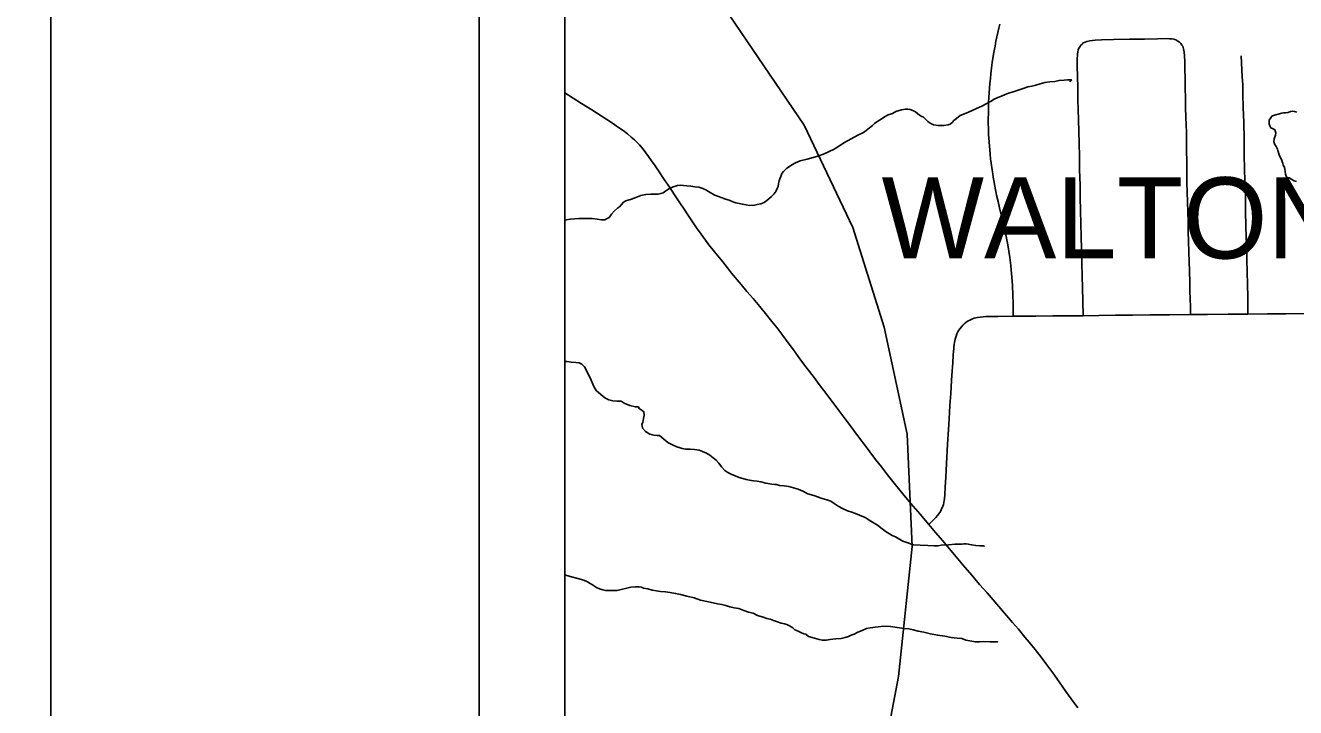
# Model space of a CAD drawing. Extents: x 0 to 34, y 0 to 22.
# Drawn here: x 1.47 to 2.953, y 15.914 to 16.711 of the extents above; entities that cross this region are included whole.
import ezdxf

# ---------------------------------------------------------------- set-up
doc = ezdxf.new("R2010")
doc.units = 0
for name, color, linetype in [('GM_X_City_Street', 7, 'Continuous'), ('GM_X_Corporation_Text', 7, 'Continuous'), ('GM_X_County_Road', 7, 'Continuous'), ('GM_X_County_Text', 7, 'Continuous'), ('GM_X_Minor_Lake', 7, 'Continuous'), ('GM_X_Minor_River', 7, 'Continuous'), ('GM_X_Rail_Line', 7, 'Continuous'), ('SH_Border', 7, 'Continuous'), ('SH_Cut_Line', 7, 'Continuous'), ('SH_Data', 7, 'Continuous')]:
    doc.layers.add(name, color=color, linetype=linetype)

msp = doc.modelspace()

# ---------------------------------------------------------------- linework, layer by layer
at = {"layer": 'GM_X_City_Street'}
for points in [[(2.623, 16.3712), (2.6229, 16.3858), (2.6226, 16.3959), (2.6222, 16.4073), (2.6216, 16.417), (2.6209, 16.4256), (2.6203, 16.4304), (2.6191, 16.44), (2.618, 16.4472), (2.6167, 16.4545), (2.6149, 16.4644), (2.6125, 16.4755), (2.6107, 16.4831), (2.6073, 16.4978), (2.6054, 16.5052), (2.6038, 16.5126), (2.6017, 16.5232), (2.6004, 16.5296), (2.5998, 16.5338), (2.5992, 16.5375), (2.5985, 16.542), (2.5974, 16.5501), (2.5968, 16.5551), (2.5963, 16.5605), (2.595, 16.5747), (2.5944, 16.5833), (2.5942, 16.5875), (2.5941, 16.5916), (2.594, 16.5956), (2.5941, 16.6143), (2.5943, 16.6178), (2.5944, 16.6213), (2.5948, 16.6267), (2.5951, 16.6321), (2.5955, 16.6375), (2.596, 16.6431), (2.5965, 16.6488), (2.597, 16.6544), (2.5974, 16.6577), (2.5978, 16.661), (2.5982, 16.6643), (2.5987, 16.6676), (2.5998, 16.675), (2.6005, 16.6791), (2.6013, 16.6832), (2.6019, 16.6864), (2.603, 16.6923), (2.6041, 16.6973), (2.6052, 16.7024), (2.6063, 16.7074), (2.6075, 16.7124)], [(2.7011, 16.6863), (2.7022, 16.6878), (2.7035, 16.6891), (2.7048, 16.6903), (2.7069, 16.6914), (2.7091, 16.6922), (2.7124, 16.6928), (2.7156, 16.6933), (2.7189, 16.6936), (2.7261, 16.694), (2.7402, 16.6942), (2.759, 16.6946), (2.7762, 16.6949), (2.7914, 16.6952), (2.8022, 16.6954), (2.8054, 16.6953), (2.8078, 16.6951), (2.8104, 16.6946), (2.8129, 16.6938), (2.8151, 16.6926), (2.817, 16.6913), (2.8186, 16.6897), (2.8199, 16.6879), (2.821, 16.6864)], [(2.7046, 16.3719), (2.7042, 16.3892), (2.7038, 16.4044), (2.7035, 16.4179), (2.7032, 16.4336), (2.7028, 16.4494), (2.7024, 16.4646), (2.7021, 16.4795), (2.7018, 16.4942), (2.7014, 16.5097), (2.7011, 16.5243), (2.7006, 16.542), (2.7003, 16.558), (2.6999, 16.5728), (2.6996, 16.5872), (2.6993, 16.6), (2.699, 16.6131), (2.6987, 16.624), (2.6984, 16.6375), (2.6981, 16.6518), (2.6978, 16.6625), (2.6977, 16.6709), (2.698, 16.6773), (2.6984, 16.6798), (2.699, 16.6822), (2.6998, 16.6842), (2.7011, 16.6863)], [(2.8301, 16.3733), (2.8298, 16.3827), (2.8296, 16.3913), (2.8293, 16.4006), (2.8291, 16.4106), (2.8287, 16.4244), (2.8284, 16.4349), (2.8281, 16.4463), (2.8277, 16.4589), (2.8274, 16.4701), (2.8271, 16.4811), (2.8268, 16.4938), (2.8265, 16.5043), (2.8261, 16.5166), (2.8259, 16.5266), (2.8257, 16.5398), (2.8256, 16.5523), (2.8254, 16.5641), (2.8253, 16.575), (2.8252, 16.5848), (2.8249, 16.5959), (2.8247, 16.603), (2.8243, 16.6157), (2.8242, 16.6263), (2.8239, 16.6371), (2.8237, 16.6487), (2.8234, 16.6594), (2.8232, 16.6684), (2.823, 16.6751), (2.8227, 16.6794), (2.8224, 16.6815), (2.822, 16.6836), (2.8216, 16.685), (2.821, 16.6864)], [(2.8969, 16.3738), (2.8967, 16.3923), (2.8964, 16.4099), (2.8962, 16.4217), (2.8958, 16.4384), (2.8954, 16.4545), (2.8947, 16.4752), (2.8942, 16.4949), (2.894, 16.5085), (2.8936, 16.5234), (2.893, 16.5408), (2.8927, 16.5618), (2.8925, 16.5783), (2.8921, 16.5976), (2.8915, 16.615), (2.8912, 16.6305), (2.8911, 16.6363), (2.8909, 16.6419), (2.8904, 16.6509), (2.8896, 16.667), (2.8892, 16.6751)]]:
    msp.add_lwpolyline(points, dxfattribs=at)
at = {"layer": 'GM_X_County_Road'}
for points in [[(2.6985, 15.914), (2.6909, 15.9245), (2.6846, 15.9332), (2.6766, 15.9444), (2.6692, 15.9547), (2.6612, 15.9658), (2.6556, 15.9732), (2.6488, 15.9822), (2.6419, 15.9907), (2.6368, 15.9966), (2.6292, 16.0059), (2.6223, 16.0138), (2.6129, 16.0246), (2.5972, 16.0427), (2.5926, 16.0482), (2.5838, 16.0582), (2.5748, 16.0688), (2.5643, 16.0811), (2.5565, 16.0904), (2.5484, 16.1001), (2.5408, 16.109), (2.5325, 16.1188), (2.5248, 16.1279), (2.5144, 16.1401), (2.5038, 16.1527), (2.4944, 16.1639), (2.4856, 16.1745), (2.4764, 16.186), (2.4693, 16.1953), (2.4626, 16.204), (2.4559, 16.213), (2.4504, 16.2203), (2.4439, 16.2289), (2.4372, 16.2378), (2.4316, 16.2452), (2.4256, 16.2534), (2.4198, 16.2611), (2.4141, 16.2686), (2.4078, 16.2767), (2.402, 16.2844), (2.3977, 16.29), (2.3895, 16.3011), (2.3797, 16.3143), (2.3723, 16.3243), (2.3666, 16.3321), (2.3606, 16.3401), (2.3531, 16.3502), (2.3471, 16.3581), (2.34, 16.3671), (2.3342, 16.3744), (2.3275, 16.3826), (2.3198, 16.3918), (2.3124, 16.4003), (2.3058, 16.4083), (2.2945, 16.4217), (2.2898, 16.4277), (2.2842, 16.4346), (2.2746, 16.4466), (2.2681, 16.4548), (2.2639, 16.4602), (2.2589, 16.467), (2.2537, 16.4746), (2.249, 16.4815), (2.2434, 16.4897), (2.2392, 16.4961), (2.2341, 16.5037), (2.228, 16.5128), (2.2223, 16.5215), (2.216, 16.5309), (2.2092, 16.5409), (2.2052, 16.5468), (2.2012, 16.5527), (2.1976, 16.5579), (2.1945, 16.5622), (2.1912, 16.5664), (2.1869, 16.5714), (2.1846, 16.5739), (2.1811, 16.5772), (2.1775, 16.5805), (2.1731, 16.5841), (2.1679, 16.588), (2.1627, 16.5917), (2.1556, 16.5965), (2.1425, 16.6052), (2.1315, 16.6121), (2.1194, 16.6197), (2.1097, 16.6258), (2.1, 16.632)], [(2.5248, 16.1279), (2.5327, 16.1361), (2.5348, 16.1386), (2.5374, 16.1422), (2.5386, 16.1441), (2.5396, 16.1462), (2.5405, 16.1483), (2.5416, 16.1515), (2.5422, 16.1537), (2.5427, 16.1559), (2.5429, 16.1581), (2.5433, 16.163), (2.5439, 16.1718), (2.5445, 16.1835), (2.5453, 16.1991), (2.5466, 16.222), (2.5476, 16.2388), (2.5483, 16.2516), (2.5493, 16.2672), (2.5502, 16.281), (2.5511, 16.2961), (2.5519, 16.3074), (2.5526, 16.317), (2.5531, 16.3258), (2.5534, 16.3303), (2.5537, 16.3332), (2.554, 16.3357), (2.5543, 16.3381), (2.5546, 16.3406), (2.5554, 16.3444), (2.5565, 16.3481), (2.5575, 16.3505), (2.5586, 16.3529), (2.5598, 16.355), (2.5612, 16.357), (2.5627, 16.3589), (2.5643, 16.3607), (2.566, 16.3623), (2.5678, 16.3638), (2.5706, 16.3657), (2.5725, 16.3667), (2.5756, 16.3681), (2.5777, 16.3688), (2.5814, 16.3696), (2.5846, 16.3702), (2.5879, 16.3706), (2.5911, 16.3708), (2.6051, 16.371), (2.623, 16.3712), (2.6363, 16.3713), (2.6495, 16.3714), (2.6692, 16.3716), (2.6856, 16.3717), (2.7046, 16.3719), (2.7232, 16.3721), (2.7423, 16.3723), (2.7622, 16.3725), (2.783, 16.3727), (2.8056, 16.373), (2.8301, 16.3733), (2.85, 16.3734), (2.8741, 16.3736), (2.8969, 16.3738), (2.9198, 16.374), (2.9417, 16.3742), (2.9648, 16.3744)]]:
    msp.add_lwpolyline(points, dxfattribs=at)
at = {"layer": 'GM_X_County_Text'}
msp.add_lwpolyline([(8.9, 20.9), (2.1, 20.9), (2.1, 15.3556)], dxfattribs=at)
at = {"layer": 'GM_X_Minor_Lake'}
for points in [[(2.932, 16.5648), (2.9316, 16.5662), (2.9301, 16.5696), (2.9285, 16.5718), (2.9273, 16.5748), (2.9277, 16.5783), (2.9291, 16.5825), (2.9295, 16.5855), (2.9283, 16.5889), (2.9264, 16.59), (2.9237, 16.5912), (2.9226, 16.5934), (2.9218, 16.5957), (2.9217, 16.6003), (2.9236, 16.6029), (2.9254, 16.6052)], [(2.9254, 16.6051), (2.9364, 16.6084), (2.9387, 16.6088), (2.9413, 16.6089), (2.944, 16.6093), (2.9466, 16.6101), (2.9485, 16.6105), (2.9512, 16.6101), (2.9542, 16.6094)], [(2.9538, 16.5284), (2.9511, 16.5295), (2.9484, 16.531), (2.945, 16.5329), (2.9419, 16.5336), (2.9407, 16.537), (2.9403, 16.5404), (2.9399, 16.5427), (2.9395, 16.5453), (2.9383, 16.5476), (2.9379, 16.5499), (2.9371, 16.5521), (2.936, 16.5544), (2.9348, 16.5571), (2.9336, 16.5597), (2.932, 16.5648)]]:
    msp.add_lwpolyline(points, dxfattribs=at)
at = {"layer": 'GM_X_Minor_River'}
for points in [[(2.5917, 16.6192), (2.5966, 16.622), (2.6007, 16.6247), (2.6053, 16.6266), (2.6094, 16.6282), (2.6136, 16.6302), (2.6177, 16.6317), (2.6219, 16.6329), (2.6358, 16.6377), (2.64, 16.6389), (2.6449, 16.6397), (2.6495, 16.6409), (2.6544, 16.6425), (2.6601, 16.6441), (2.6657, 16.6449), (2.6718, 16.6454), (2.6767, 16.6466), (2.6824, 16.647), (2.6866, 16.6474), (2.6892, 16.6471), (2.6911, 16.6471), (2.6907, 16.6475), (2.6911, 16.6471), (2.6893, 16.6448)], [(2.1776, 16.5078), (2.1829, 16.5098), (2.1885, 16.5122), (2.1946, 16.5134), (2.2003, 16.5138), (2.2048, 16.5139), (2.209, 16.5139), (2.212, 16.5147), (2.2147, 16.5155), (2.2177, 16.5175), (2.2222, 16.5202), (2.2264, 16.5225), (2.2313, 16.5237), (2.2343, 16.5241), (2.2423, 16.5235), (2.2468, 16.5232), (2.2518, 16.5225), (2.2563, 16.5218), (2.2609, 16.5203), (2.2644, 16.5188), (2.2674, 16.517), (2.2716, 16.5144), (2.2751, 16.5125), (2.2793, 16.511), (2.2835, 16.5096), (2.2873, 16.5081), (2.2915, 16.5066), (2.2953, 16.5052), (2.2995, 16.5037), (2.3033, 16.503), (2.3071, 16.5019), (2.3116, 16.5012), (2.3158, 16.5005), (2.3211, 16.5009), (2.3245, 16.5017), (2.3287, 16.5025), (2.3325, 16.5041), (2.3355, 16.5064), (2.3381, 16.5084), (2.3411, 16.5111), (2.3437, 16.5138), (2.346, 16.5168), (2.3478, 16.5203), (2.3489, 16.5226), (2.3493, 16.5264), (2.35, 16.5294), (2.3507, 16.5317), (2.3518, 16.5344), (2.3533, 16.5378), (2.3552, 16.5401), (2.357, 16.5421), (2.3589, 16.544), (2.3619, 16.5459), (2.3649, 16.5479), (2.3691, 16.5502), (2.3747, 16.5526), (2.3827, 16.5546), (2.3951, 16.5582), (2.4016, 16.5605), (2.414, 16.5664), (2.4261, 16.5741), (2.4419, 16.5827), (2.4483, 16.5858), (2.4517, 16.5882), (2.4554, 16.5912), (2.4588, 16.594), (2.4614, 16.5963), (2.4641, 16.5982), (2.4671, 16.6001), (2.4701, 16.6021), (2.4731, 16.604), (2.4773, 16.6064), (2.4822, 16.6079), (2.4863, 16.6103), (2.4927, 16.6123), (2.4973, 16.6131), (2.5003, 16.6131), (2.503, 16.6128), (2.506, 16.6113), (2.5091, 16.6098), (2.5114, 16.6079), (2.5137, 16.6061), (2.5164, 16.6046), (2.5183, 16.6035), (2.5217, 16.6005), (2.5236, 16.5986), (2.5263, 16.5967), (2.5301, 16.5949), (2.5359, 16.5938), (2.5423, 16.5939), (2.5472, 16.5947), (2.5495, 16.5955), (2.5517, 16.5974), (2.554, 16.5997), (2.557, 16.6021), (2.5611, 16.6055), (2.5683, 16.6083), (2.5743, 16.611), (2.5804, 16.6138), (2.5864, 16.6165), (2.5917, 16.6192)], [(2.1, 16.4833), (2.102, 16.4837), (2.1062, 16.4845), (2.1111, 16.4849), (2.1164, 16.4854), (2.1217, 16.4854), (2.1267, 16.4855), (2.132, 16.4852), (2.1377, 16.4845), (2.1426, 16.4838), (2.1464, 16.4839), (2.1487, 16.485), (2.1517, 16.4866), (2.1543, 16.4904), (2.158, 16.4943), (2.1614, 16.4974), (2.1637, 16.4989), (2.1659, 16.5016), (2.1685, 16.5043), (2.1712, 16.5058), (2.1776, 16.5078)], [(2.1, 16.3183), (2.1026, 16.3182), (2.1072, 16.3175), (2.1129, 16.3172), (2.1167, 16.3169), (2.1198, 16.3154), (2.1228, 16.312), (2.1252, 16.3079), (2.1267, 16.3045), (2.1287, 16.3007), (2.1306, 16.2965), (2.1326, 16.292), (2.1345, 16.2878), (2.1369, 16.2841), (2.1465, 16.2758), (2.1514, 16.2736), (2.156, 16.2725), (2.1609, 16.2722), (2.1636, 16.2719), (2.1655, 16.2719), (2.1693, 16.2697), (2.1758, 16.2671), (2.1823, 16.2653), (2.1857, 16.2653), (2.1865, 16.2634), (2.1903, 16.2612), (2.1922, 16.2597), (2.1926, 16.2555), (2.1916, 16.2517), (2.1908, 16.2471), (2.1897, 16.2452), (2.1906, 16.2406), (2.194, 16.2365), (2.199, 16.2335), (2.2039, 16.2324), (2.2077, 16.2321), (2.2104, 16.2318), (2.2154, 16.2276), (2.22, 16.2239), (2.2257, 16.2209), (2.2307, 16.2187), (2.2345, 16.2176), (2.2368, 16.2169), (2.2406, 16.2162), (2.2463, 16.2159), (2.2512, 16.2156)], [(2.2512, 16.2156), (2.2565, 16.2149), (2.2604, 16.2134), (2.2653, 16.2112), (2.2691, 16.2089), (2.273, 16.2059), (2.2764, 16.2033), (2.2795, 16.1996), (2.2826, 16.1954), (2.2868, 16.1913), (2.2903, 16.1887), (2.2941, 16.1868), (2.2987, 16.185), (2.3033, 16.1831), (2.3078, 16.1817), (2.3116, 16.1806), (2.3154, 16.1799), (2.32, 16.1792), (2.3242, 16.1788), (2.3287, 16.1778), (2.3345, 16.1763), (2.3413, 16.1752), (2.3451, 16.1749), (2.347, 16.1746), (2.3504, 16.1738), (2.3557, 16.1732), (2.3611, 16.1725), (2.3668, 16.171), (2.3721, 16.1692), (2.3775, 16.167), (2.3836, 16.164), (2.3904, 16.1618), (2.4, 16.1585), (2.4057, 16.1567), (2.4102, 16.1552), (2.4141, 16.1526), (2.4187, 16.1496), (2.424, 16.1466), (2.4297, 16.1441), (2.4347, 16.1426), (2.4389, 16.1411), (2.4439, 16.1389), (2.4503, 16.1363), (2.4568, 16.1319), (2.4649, 16.1274), (2.4702, 16.1229), (2.4748, 16.1195), (2.4787, 16.1173), (2.4817, 16.1154), (2.484, 16.1143), (2.4859, 16.1136), (2.4943, 16.1088), (2.4989, 16.1069), (2.5043, 16.1051), (2.5069, 16.1043), (2.5145, 16.1041), (2.5236, 16.1034), (2.5312, 16.1031), (2.5354, 16.1032), (2.5392, 16.104), (2.5475, 16.1045), (2.5551, 16.105), (2.5604, 16.105), (2.5635, 16.1051), (2.5657, 16.1055), (2.5684, 16.1055), (2.5707, 16.1052), (2.5745, 16.1045), (2.5794, 16.1034), (2.5843, 16.1031), (2.5878, 16.1031), (2.5881, 16.1031), (2.5893, 16.1027), (2.5897, 16.1024)], [(2.1, 16.0693), (2.1063, 16.0673), (2.115, 16.0651), (2.1219, 16.0629), (2.1265, 16.0611), (2.1295, 16.0592), (2.1322, 16.0577), (2.1345, 16.0562), (2.1368, 16.0544), (2.1402, 16.0529), (2.1444, 16.0518), (2.1475, 16.0511), (2.1517, 16.0511), (2.1558, 16.0512), (2.1608, 16.0512), (2.177, 16.0549), (2.182, 16.0553), (2.1865, 16.0554), (2.1892, 16.055), (2.1918, 16.0539), (2.1968, 16.0528), (2.2017, 16.0514), (2.2067, 16.0507), (2.2116, 16.05), (2.2173, 16.0493), (2.223, 16.0486), (2.2291, 16.0476), (2.2348, 16.0465), (2.2424, 16.0443), (2.2508, 16.0425), (2.2581, 16.0399), (2.2676, 16.0378), (2.2729, 16.0367), (2.2782, 16.0356), (2.2832, 16.0346), (2.2877, 16.0335), (2.2923, 16.032), (2.2976, 16.0309), (2.303, 16.0299), (2.3087, 16.0277), (2.3144, 16.0258), (2.3197, 16.0244), (2.3247, 16.0218), (2.3312, 16.02)], [(2.3312, 16.02), (2.3357, 16.0185), (2.3396, 16.0174), (2.3434, 16.0159), (2.3479, 16.0145), (2.3525, 16.013), (2.3563, 16.0119), (2.359, 16.0112), (2.362, 16.0097), (2.3659, 16.0075), (2.3682, 16.0052), (2.372, 16.0037), (2.3754, 16.0019), (2.3789, 16.0004), (2.3811, 16.0001), (2.3842, 15.9974), (2.3911, 15.9952), (2.3968, 15.9938), (2.4002, 15.9931), (2.4025, 15.9931), (2.4051, 15.9931), (2.4093, 15.9936), (2.4161, 15.9944), (2.4222, 15.9949), (2.4271, 15.9961), (2.4309, 15.9973), (2.4339, 15.9988), (2.4377, 16), (2.4418, 16.0024), (2.4467, 16.0043), (2.452, 16.0067), (2.4562, 16.0075), (2.4592, 16.0079), (2.4619, 16.0083), (2.4657, 16.0087), (2.4721, 16.0092), (2.4801, 16.0089), (2.4877, 16.0079), (2.496, 16.0068), (2.5014, 16.0062), (2.5063, 16.0051), (2.5124, 16.0036), (2.5189, 16.0022), (2.5265, 16.0004), (2.5349, 15.999), (2.5432, 15.9976), (2.5508, 15.9961), (2.5577, 15.9955), (2.563, 15.9948), (2.5679, 15.9929), (2.5748, 15.9919), (2.5786, 15.9912), (2.5816, 15.9912), (2.5839, 15.9909), (2.5888, 15.9913), (2.5964, 15.991), (2.6025, 15.9911), (2.6048, 15.9911), (2.6048, 15.9911), (2.6048, 15.9915)]]:
    msp.add_lwpolyline(points, dxfattribs=at)
at = {"layer": 'GM_X_Rail_Line'}
msp.add_lwpolyline([(2.3828, 15.3572), (2.4036, 15.4999), (2.4892, 15.9504), (2.5052, 16.1024), (2.4992, 16.2334), (2.4726, 16.3585), (2.4359, 16.4747), (2.3792, 16.5945), (2.2851, 16.7329), (2.1, 17.0033)], dxfattribs=at)
at = {"layer": 'SH_Border'}
for points in [[(0.5, 21.5), (1.5, 21.5), (1.5, 0.5), (0.5, 0.5)], [(1.5, 21.5), (33.5, 21.5), (33.5, 0.5), (1.5, 0.5)]]:
    msp.add_lwpolyline(points, close=True, dxfattribs=at)
at = {"layer": 'SH_Cut_Line'}
msp.add_lwpolyline([(8.9, 20.9), (2.1, 20.9), (2.1, 15.3556)], dxfattribs=at)
at = {"layer": 'SH_Data'}
for p, q in [((2, 21), (2, 14)), ((2.1, 20.9), (2.1, 14.1))]:
    msp.add_line(p, q, dxfattribs=at)

# ---------------------------------------------------------------- texts
at = {"layer": 'GM_X_Corporation_Text'}
msp.add_text('WALTON HILLS', height=0.094697, rotation=0, dxfattribs=at).set_placement((2.4695, 16.4387))

doc.saveas('drawing.dxf')
